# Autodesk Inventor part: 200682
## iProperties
Created: 2007-10
Part Number: 200682
Document SubType Name: Modeling
Designer: TH
Density: 7.85 g/cm^3
Mass: 382.443 g
Surface Area: 158.814 cm^2
Volume: 48.7189 cm^3
Material: Steel
Description: SUPPORT ROD
Component Category: Lower Component
Author: TH
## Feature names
1. Revolution1
2. Chamfer1
3. Fillet1
4. Chamfer2
5. Split1
